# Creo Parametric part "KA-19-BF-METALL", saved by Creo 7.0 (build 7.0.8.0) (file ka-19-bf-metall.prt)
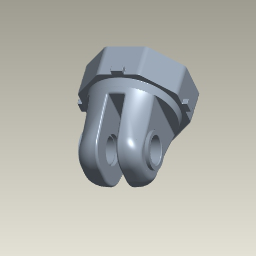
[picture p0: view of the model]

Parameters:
  PTC_COMMON_NAME = "ka-19-bf-metall.prt"
  PTC_WM_REVISION = "A"
  PTC_WM_ITERATION = "1"
  PTC_WM_VERSION = "A.1"
  PTC_WM_LIFECYCLE_STATE = "Concept"
  PTC_WM_LIFECYCLE = "Life Cycle Schema Type 1"
  PTC_WM_LOCATION = "/Products/KA19_CN2215/CAD"
  PTC_WM_CREATED_BY = "Jörg Monien"
  PTC_WM_CREATED_ON = "2026-08-11"
  PTC_WM_MODIFIED_BY = "Jörg Monien"
  PTC_WM_MODIFIED_ON = "2026-08-11"
  PTC_WM_TEAM = "Default"
  PTC_WM_NAME = "ka-19-bf-metall.prt"
  PTC_WM_NUMBER = "KA-19-BF-METALL.PRT"
  PDMREV = "A.1+"
  PDMRL = "Concept"
  PROI_REVISION = "A"
  PROI_VERSION = "1"
  PROI_RELEASE = "Concept"

Created from: START_PART.PRT

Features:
  1. datum plane "RIGHT"
  2. datum plane "TOP"
  3. datum plane "FRONT"
  4. coordinate system
  5. datum axis
  6. datum axis
  7. datum axis
  8. imported feature "Import Feature id 12059"
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
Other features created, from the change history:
  feature "Copy Geometry id 47"
  patch "Solidify 1"
  coordinate system "CS1" (2 times)
  datum axis "A_1"
  datum axis "A_2"
  datum plane "DTM1"
  datum axis "A_3"
  extrusion "Extrude 1" (2 times)
  imported feature "Import Feature id 6456"
  feature "External Add Bodies id 11444"
  feature "External Add Bodies id 11523"
  imported feature "Import Feature id 11603"
  imported feature "Import Feature id 29730"

Other named items: X-AXES, Y-AXES, Z-AXES, CS0, WO-BUSHING

Layers: ANNOTATIONS, AXES, COSMETICS, CSYS, CURVES, EXT_COPY_GEOM, PLANES, POINTS, PUBLISHED_GEOM, QUILTS, SOLIDS, STARTUP

Notes: NOT SPECIFIED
